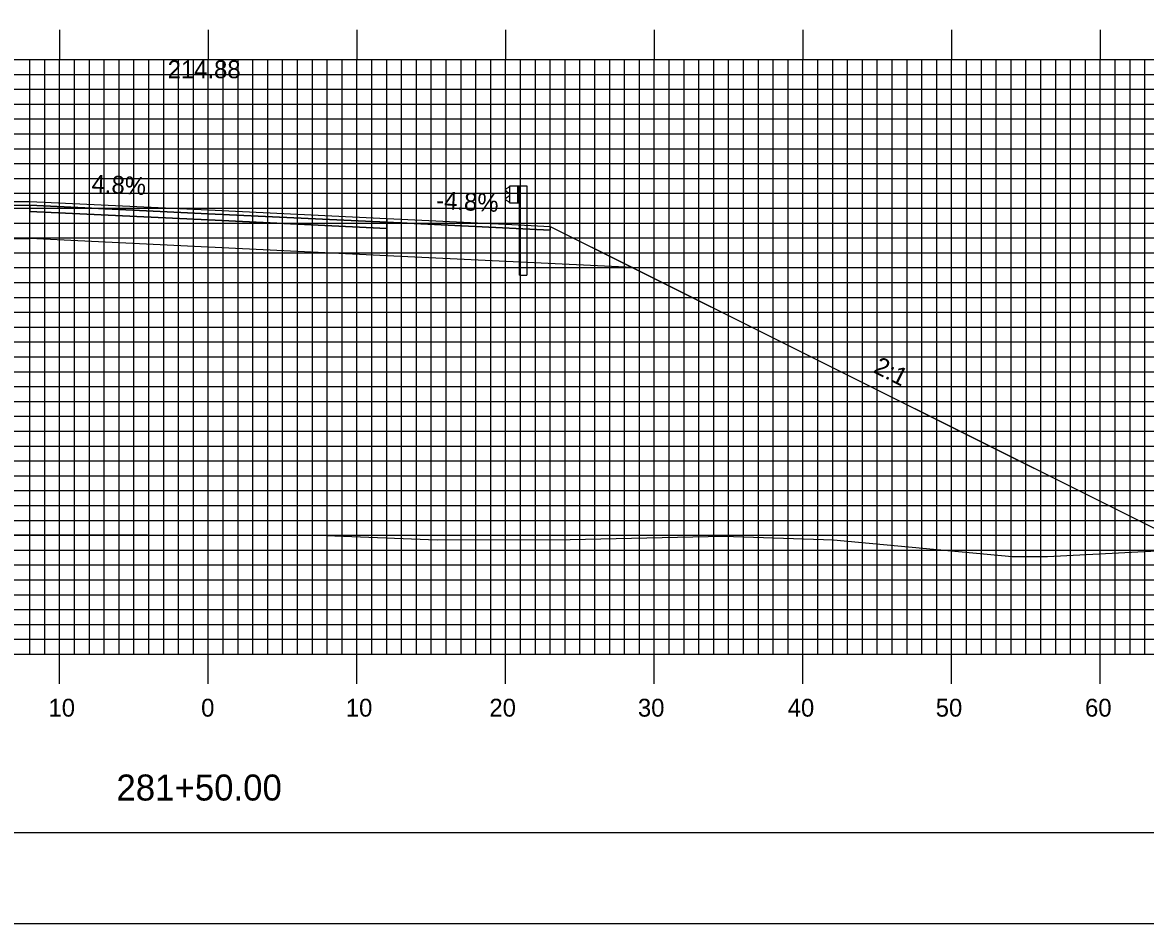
# Model space of a CAD drawing. Extents: x 1811374 to 1811717, y 442591 to 442811.
# Drawn here: x 1811526.9 to 1811602.4, y 442590.5 to 442651.2 of the extents above; entities that cross this region are included whole.
import ezdxf

# ---------------------------------------------------------------- set-up
doc = ezdxf.new("R2010")
doc.units = 0
for name, color, linetype in [('ANNOTATION', 7, 'Continuous'), ('BORDER', 7, 'Continuous'), ('D_Guardrail_Beam_Rt', 7, 'Continuous'), ('D_Roadway_Centerline', 7, 'Continuous'), ('D_Roadway_Centerline_Text', 7, 'Continuous'), ('D_Roadway_Edge_Shoulder', 7, 'Continuous'), ('D_Roadway_Edge_TW', 7, 'Continuous'), ('D_Roadway_Pavement', 7, 'Continuous'), ('D_Roadway_SlopeLines', 7, 'Continuous'), ('D_Roadway_SubGrade', 7, 'Continuous'), ('H_V ANNOTATION', 7, 'Continuous'), ('MAJOR', 7, 'Continuous'), ('MINOR', 7, 'Continuous'), ('PLOT BOUNDARY', 7, 'Continuous'), ('S_Roadway_Centerline', 7, 'Continuous')]:
    doc.layers.add(name, color=color, linetype=linetype)

msp = doc.modelspace()

# ---------------------------------------------------------------- linework, layer by layer
at = {"layer": 'BORDER'}
msp.add_lwpolyline([(1811389.803, 442596.665), (1811709.803, 442596.665), (1811709.803, 442806.665), (1811389.803, 442806.665)], close=True, dxfattribs=at)
at = {"layer": 'D_Guardrail_Beam_Rt'}
for p, q in [((1811559.584, 442640.064), (1811559.44, 442639.964)), ((1811559.44, 442639.821), (1811559.636, 442639.684)), ((1811559.636, 442639.485), (1811559.44, 442639.349)), ((1811559.674, 442640.085), (1811559.599, 442640.07)), ((1811559.669, 442639.62), (1811559.669, 442639.55)), ((1811559.674, 442640.168), (1811560.361, 442640.168)), ((1811559.674, 442639.002), (1811559.674, 442640.168)), ((1811560.194, 442640.168), (1811560.194, 442639.002)), ((1811560.299, 442640.168), (1811560.299, 442639.002)), ((1811560.361, 442640.168), (1811560.832, 442640.168)), ((1811560.361, 442640.168), (1811560.361, 442639.002)), ((1811560.832, 442640.168), (1811560.832, 442634.168)), ((1811559.44, 442639.206), (1811559.584, 442639.106)), ((1811559.599, 442639.1), (1811559.674, 442639.085)), ((1811560.361, 442639.002), (1811559.674, 442639.002)), ((1811560.34, 442634.168), (1811560.34, 442639.002)), ((1811560.34, 442634.168), (1811560.832, 442634.168))]:
    msp.add_line(p, q, dxfattribs=at)
for centre, major_axis, start_param, end_param in [((1811559.49, 442639.892), (-0.0877, 0), 5.323254, 7.243116), ((1811559.608, 442640.03), (-0.0417, 0), 4.907132, 5.323254), ((1811559.59, 442639.62), (0.0789, 0), 0, 0.959931), ((1811559.59, 442639.55), (0.0789, 0), 5.323254, 6.283185), ((1811559.49, 442639.278), (-0.0877, 0), 5.323254, 7.243116), ((1811559.608, 442639.14), (-0.0417, 0), 0.959931, 1.376053)]:
    msp.add_ellipse(centre, major_axis=major_axis, ratio=0.995501, start_param=start_param, end_param=end_param, dxfattribs=at)
at = {"layer": 'D_Roadway_Centerline'}
msp.add_lwpolyline([(1811469.899, 442615.649), (1811511.194, 442636.297), (1811516.403, 442638.901), (1811519.403, 442638.961), (1811527.403, 442639.121), (1811539.403, 442638.545), (1811551.403, 442637.969), (1811559.403, 442637.585), (1811562.403, 442637.441), (1811567.934, 442634.675), (1811605.839, 442615.723)], dxfattribs=at)
at = {"layer": 'D_Roadway_Edge_Shoulder'}
for points in [[(1811527.403, 442639.121), (1811519.403, 442638.961), (1811519.403, 442638.961), (1811516.403, 442638.901), (1811516.403, 442638.651), (1811527.403, 442638.871)], [(1811551.403, 442637.969), (1811559.403, 442637.585), (1811559.403, 442637.585), (1811562.403, 442637.441), (1811562.403, 442637.191), (1811551.403, 442637.719)]]:
    msp.add_lwpolyline(points, close=True, dxfattribs=at)
at = {"layer": 'D_Roadway_Edge_TW'}
msp.add_lwpolyline([(1811527.403, 442638.871), (1811527.403, 442639.121), (1811539.403, 442638.545), (1811551.403, 442637.969), (1811551.403, 442637.719), (1811539.403, 442638.295)], close=True, dxfattribs=at)
at = {"layer": 'D_Roadway_Pavement'}
msp.add_lwpolyline([(1811527.403, 442638.454), (1811527.403, 442638.871), (1811539.403, 442638.295), (1811551.403, 442637.719), (1811551.403, 442637.302), (1811539.403, 442637.878)], close=True, dxfattribs=at)
for points in [[(1811527.403, 442638.871), (1811527.403, 442638.454)], [(1811551.403, 442637.719), (1811551.403, 442637.302)]]:
    msp.add_lwpolyline(points, dxfattribs=at)
at = {"layer": 'D_Roadway_SlopeLines'}
msp.add_lwpolyline([(1811562.403, 442637.441), (1811605.839, 442615.723)], dxfattribs=at)
at = {"layer": 'D_Roadway_SubGrade'}
for points in [[(1811527.403, 442638.454), (1811527.403, 442638.871), (1811516.403, 442638.651), (1811516.403, 442638.901), (1811511.194, 442636.297), (1811527.403, 442636.621)], [(1811527.403, 442636.621), (1811527.403, 442638.871), (1811527.403, 442638.454), (1811539.403, 442637.878), (1811551.403, 442637.302), (1811551.403, 442637.719), (1811551.403, 442635.469), (1811539.403, 442636.045)], [(1811551.403, 442637.302), (1811551.403, 442637.719), (1811562.403, 442637.191), (1811562.403, 442637.441), (1811567.934, 442634.675), (1811551.403, 442635.469)]]:
    msp.add_lwpolyline(points, close=True, dxfattribs=at)
at = {"layer": 'MAJOR'}
for p, q in [((1811529.403, 442650.669), (1811529.403, 442648.665)), ((1811539.403, 442650.669), (1811539.403, 442648.665)), ((1811549.403, 442650.669), (1811549.403, 442648.665)), ((1811559.403, 442650.669), (1811559.403, 442648.665)), ((1811569.403, 442650.669), (1811569.403, 442648.665)), ((1811579.403, 442650.669), (1811579.403, 442648.665)), ((1811589.403, 442650.669), (1811589.403, 442648.665)), ((1811599.403, 442650.669), (1811599.403, 442648.665)), ((1811399.403, 442648.665), (1811679.403, 442648.665)), ((1811399.403, 442648.665), (1811679.403, 442648.665)), ((1811529.403, 442608.665), (1811529.403, 442648.665)), ((1811539.403, 442608.665), (1811539.403, 442648.665)), ((1811549.403, 442608.665), (1811549.403, 442648.665)), ((1811559.403, 442608.665), (1811559.403, 442648.665)), ((1811569.403, 442608.665), (1811569.403, 442648.665)), ((1811579.403, 442608.665), (1811579.403, 442648.665)), ((1811589.403, 442608.665), (1811589.403, 442648.665)), ((1811599.403, 442608.665), (1811599.403, 442648.665)), ((1811399.403, 442643.665), (1811679.403, 442643.665)), ((1811399.403, 442638.665), (1811679.403, 442638.665)), ((1811399.403, 442633.665), (1811679.403, 442633.665)), ((1811399.403, 442628.665), (1811679.403, 442628.665)), ((1811399.403, 442623.665), (1811679.403, 442623.665)), ((1811399.403, 442618.665), (1811679.403, 442618.665)), ((1811399.403, 442613.665), (1811679.403, 442613.665)), ((1811399.403, 442608.665), (1811679.403, 442608.665)), ((1811399.403, 442608.665), (1811679.403, 442608.665)), ((1811529.403, 442606.661), (1811529.403, 442608.665)), ((1811539.403, 442606.661), (1811539.403, 442608.665)), ((1811549.403, 442606.661), (1811549.403, 442608.665)), ((1811559.403, 442606.661), (1811559.403, 442608.665)), ((1811569.403, 442606.661), (1811569.403, 442608.665)), ((1811579.403, 442606.661), (1811579.403, 442608.665)), ((1811589.403, 442606.661), (1811589.403, 442608.665)), ((1811599.403, 442606.661), (1811599.403, 442608.665))]:
    msp.add_line(p, q, dxfattribs=at)
at = {"layer": 'MINOR'}
for p, q in [((1811527.403, 442608.665), (1811527.403, 442648.665)), ((1811528.403, 442608.665), (1811528.403, 442648.665)), ((1811530.403, 442608.665), (1811530.403, 442648.665)), ((1811531.403, 442608.665), (1811531.403, 442648.665)), ((1811532.403, 442608.665), (1811532.403, 442648.665)), ((1811533.403, 442608.665), (1811533.403, 442648.665)), ((1811534.403, 442608.665), (1811534.403, 442648.665)), ((1811535.403, 442608.665), (1811535.403, 442648.665)), ((1811536.403, 442608.665), (1811536.403, 442648.665)), ((1811537.403, 442608.665), (1811537.403, 442648.665)), ((1811538.403, 442608.665), (1811538.403, 442648.665)), ((1811540.403, 442608.665), (1811540.403, 442648.665)), ((1811541.403, 442608.665), (1811541.403, 442648.665)), ((1811542.403, 442608.665), (1811542.403, 442648.665)), ((1811543.403, 442608.665), (1811543.403, 442648.665)), ((1811544.403, 442608.665), (1811544.403, 442648.665)), ((1811545.403, 442608.665), (1811545.403, 442648.665)), ((1811546.403, 442608.665), (1811546.403, 442648.665)), ((1811547.403, 442608.665), (1811547.403, 442648.665)), ((1811548.403, 442608.665), (1811548.403, 442648.665)), ((1811550.403, 442608.665), (1811550.403, 442648.665)), ((1811551.403, 442608.665), (1811551.403, 442648.665)), ((1811552.403, 442608.665), (1811552.403, 442648.665)), ((1811553.403, 442608.665), (1811553.403, 442648.665)), ((1811554.403, 442608.665), (1811554.403, 442648.665)), ((1811555.403, 442608.665), (1811555.403, 442648.665)), ((1811556.403, 442608.665), (1811556.403, 442648.665)), ((1811557.403, 442608.665), (1811557.403, 442648.665)), ((1811558.403, 442608.665), (1811558.403, 442648.665)), ((1811560.403, 442608.665), (1811560.403, 442648.665)), ((1811561.403, 442608.665), (1811561.403, 442648.665)), ((1811562.403, 442608.665), (1811562.403, 442648.665)), ((1811563.403, 442608.665), (1811563.403, 442648.665)), ((1811564.403, 442608.665), (1811564.403, 442648.665)), ((1811565.403, 442608.665), (1811565.403, 442648.665)), ((1811566.403, 442608.665), (1811566.403, 442648.665)), ((1811567.403, 442608.665), (1811567.403, 442648.665)), ((1811568.403, 442608.665), (1811568.403, 442648.665)), ((1811570.403, 442608.665), (1811570.403, 442648.665)), ((1811571.403, 442608.665), (1811571.403, 442648.665)), ((1811572.403, 442608.665), (1811572.403, 442648.665)), ((1811573.403, 442608.665), (1811573.403, 442648.665)), ((1811574.403, 442608.665), (1811574.403, 442648.665)), ((1811575.403, 442608.665), (1811575.403, 442648.665)), ((1811576.403, 442608.665), (1811576.403, 442648.665)), ((1811577.403, 442608.665), (1811577.403, 442648.665)), ((1811578.403, 442608.665), (1811578.403, 442648.665)), ((1811580.403, 442608.665), (1811580.403, 442648.665)), ((1811581.403, 442608.665), (1811581.403, 442648.665)), ((1811582.403, 442608.665), (1811582.403, 442648.665)), ((1811583.403, 442608.665), (1811583.403, 442648.665)), ((1811584.403, 442608.665), (1811584.403, 442648.665)), ((1811585.403, 442608.665), (1811585.403, 442648.665)), ((1811586.403, 442608.665), (1811586.403, 442648.665)), ((1811587.403, 442608.665), (1811587.403, 442648.665)), ((1811588.403, 442608.665), (1811588.403, 442648.665)), ((1811590.403, 442608.665), (1811590.403, 442648.665)), ((1811591.403, 442608.665), (1811591.403, 442648.665)), ((1811592.403, 442608.665), (1811592.403, 442648.665)), ((1811593.403, 442608.665), (1811593.403, 442648.665)), ((1811594.403, 442608.665), (1811594.403, 442648.665)), ((1811595.403, 442608.665), (1811595.403, 442648.665)), ((1811596.403, 442608.665), (1811596.403, 442648.665)), ((1811597.403, 442608.665), (1811597.403, 442648.665)), ((1811598.403, 442608.665), (1811598.403, 442648.665)), ((1811600.403, 442608.665), (1811600.403, 442648.665)), ((1811601.403, 442608.665), (1811601.403, 442648.665)), ((1811602.403, 442608.665), (1811602.403, 442648.665)), ((1811399.403, 442647.665), (1811679.403, 442647.665)), ((1811399.403, 442646.665), (1811679.403, 442646.665)), ((1811399.403, 442645.665), (1811679.403, 442645.665)), ((1811399.403, 442644.665), (1811679.403, 442644.665)), ((1811399.403, 442642.665), (1811679.403, 442642.665)), ((1811399.403, 442641.665), (1811679.403, 442641.665)), ((1811399.403, 442640.665), (1811679.403, 442640.665)), ((1811399.403, 442639.665), (1811679.403, 442639.665)), ((1811399.403, 442637.665), (1811679.403, 442637.665)), ((1811399.403, 442636.665), (1811679.403, 442636.665)), ((1811399.403, 442635.665), (1811679.403, 442635.665)), ((1811399.403, 442634.665), (1811679.403, 442634.665)), ((1811399.403, 442632.665), (1811679.403, 442632.665)), ((1811399.403, 442631.665), (1811679.403, 442631.665)), ((1811399.403, 442630.665), (1811679.403, 442630.665)), ((1811399.403, 442629.665), (1811679.403, 442629.665)), ((1811399.403, 442627.665), (1811679.403, 442627.665)), ((1811399.403, 442626.665), (1811679.403, 442626.665)), ((1811399.403, 442625.665), (1811679.403, 442625.665)), ((1811399.403, 442624.665), (1811679.403, 442624.665)), ((1811399.403, 442622.665), (1811679.403, 442622.665)), ((1811399.403, 442621.665), (1811679.403, 442621.665)), ((1811399.403, 442620.665), (1811679.403, 442620.665)), ((1811399.403, 442619.665), (1811679.403, 442619.665)), ((1811399.403, 442617.665), (1811679.403, 442617.665)), ((1811399.403, 442616.665), (1811679.403, 442616.665)), ((1811399.403, 442615.665), (1811679.403, 442615.665)), ((1811399.403, 442614.665), (1811679.403, 442614.665)), ((1811399.403, 442612.665), (1811679.403, 442612.665)), ((1811399.403, 442611.665), (1811679.403, 442611.665)), ((1811399.403, 442610.665), (1811679.403, 442610.665)), ((1811399.403, 442609.665), (1811679.403, 442609.665))]:
    msp.add_line(p, q, dxfattribs=at)
at = {"layer": 'PLOT BOUNDARY'}
msp.add_lwpolyline([(1811373.616, 442590.547), (1811713.616, 442590.547), (1811713.616, 442810.547), (1811373.616, 442810.547)], close=True, dxfattribs=at)
at = {"layer": 'S_Roadway_Centerline'}
msp.add_lwpolyline([(1811466.871, 442615.608), (1811469.667, 442615.641), (1811487.909, 442616.255), (1811489.697, 442616.328), (1811489.969, 442616.334), (1811490.335, 442616.33), (1811499.486, 442616.559), (1811502.206, 442616.645), (1811510.627, 442616.872), (1811515.025, 442616.779), (1811522.234, 442616.711), (1811535.321, 442616.688), (1811546.762, 442616.669), (1811554.792, 442616.358), (1811563.75, 442616.373), (1811574.066, 442616.599), (1811581.458, 442616.355), (1811593.483, 442615.24), (1811595.845, 442615.245), (1811605.404, 442615.731)], dxfattribs=at)

# ---------------------------------------------------------------- texts
at = {"layer": 'ANNOTATION'}
for s, rotation, p in [('4.8%', 357.25191, (1811531.532, 442639.725)), ('-4.8%', 357.25191, (1811554.711, 442638.612)), ('2:1', 333.43495, (1811584.055, 442627.651))]:
    msp.add_text(s, height=1.2, rotation=rotation, dxfattribs=at).set_placement(p)
at = {"layer": 'D_Roadway_Centerline'}
for s, p in [('C', (1811539.398, 442638.545)), ('L', (1811539.403, 442638.538))]:
    msp.add_text(s, height=0.0146, dxfattribs=at).set_placement(p)
at = {"layer": 'D_Roadway_Centerline_Text'}
msp.add_text('214.88', height=1.2, dxfattribs=at).set_placement((1811536.668, 442647.406))
at = {"layer": 'H_V ANNOTATION'}
for s, height, p in [('10', 1.2, (1811528.653, 442604.465)), ('0', 1.2, (1811538.921, 442604.465)), ('10', 1.2, (1811548.653, 442604.465)), ('20', 1.2, (1811558.311, 442604.465)), ('30', 1.2, (1811568.3, 442604.465)), ('40', 1.2, (1811578.375, 442604.465)), ('50', 1.2, (1811588.332, 442604.465)), ('60', 1.2, (1811598.375, 442604.465)), ('281+50.00', 1.75, (1811533.223, 442598.821))]:
    msp.add_text(s, height=height, dxfattribs=at).set_placement(p)

doc.saveas('drawing.dxf')
